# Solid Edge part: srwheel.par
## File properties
Title: Snap Ring
Subject: Trolley Assembly
Author: kiyo
Keywords: Snap Ring
Comments: Sanp ring 2 x 14 ID
Template: metric.par
Last saved by: edge
Revision: 27
Application: Solid Edge
File Size: 0
Number of Sheets: 0
Number of Objects: 0
Username: kiyo
文書内容のタイプ: 0
Material: Steel
Face Style: Steel
Fill Style: ANSI32(Steel)
Virtual Style: Machined steel
Coef. of Thermal Exp: 1.3e-05
Thermal Conductivity: 32.0
Specific Heat: 481.0
Modulus of Elasticity: 199947953000.0
Poisson's Ratio: 0.29
Yield Stress: 262000766.0
Ultimate Stress: 358527364.0
Elongation: 0.0
Category: Snap Ring
Manager: Brian Little
Company: Wheels R Us
Density: 7800
Accuracy: 0.99
Document Number: SR-214
Revision: 1
Project Name: Trolley Wheel Assembly
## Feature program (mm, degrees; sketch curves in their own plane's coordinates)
sketch for "unnamed RevolvedProtrusion 1" plane through (0, 0, 0) normal (0, -1, 0) x-axis (1, 0, 0)
  line (-45.0388, 28.6058) -> (-43.0388, 28.6058)
  line (-43.0388, 28.6058) -> (-43.0388, 26.6058)
  line (-43.0388, 26.6058) -> (-45.0388, 26.6058)
  line (-45.0388, 26.6058) -> (-45.0388, 28.6058)
revolve "unnamed RevolvedProtrusion 1" add finite 0 deg about sketch line (-45.0388, 12.6058) -> (-34.8858, 12.6058)
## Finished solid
Body 1: solid body, 6 faces, 12 edges, 8 vertices.
  Faces by surface: plane 4, cylinder 2
  Edges by curve: line 8, circle 4
Bounding box of the edges (mm): 2.000 x 32.000 x 32.000, from (-45.0388, -16, -3.3942) to (-43.0388, 16, 28.6058).
Cylindrical faces by radius (mm): R14 x1, R16 x1
Planar faces by outward normal: +x 1, +y 1, -x 1, oblique 1
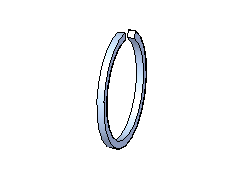
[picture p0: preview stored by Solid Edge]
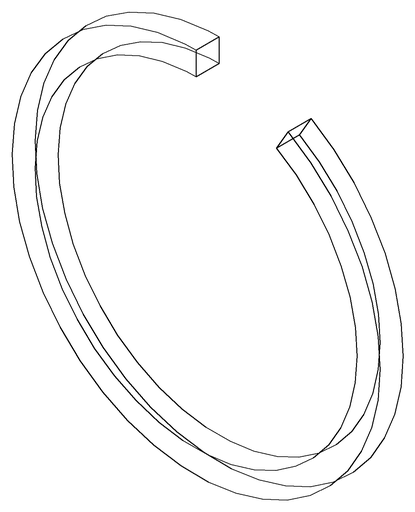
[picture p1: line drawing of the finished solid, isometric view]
